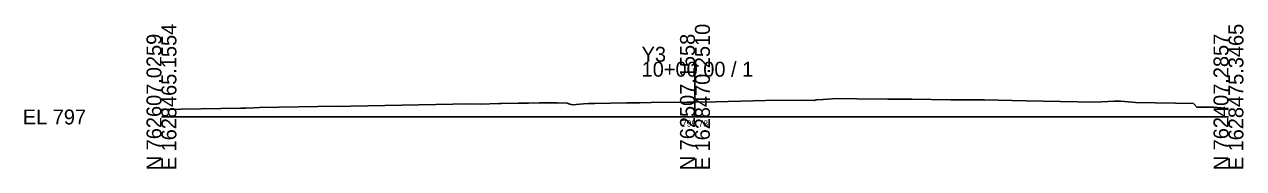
# Model space of a CAD drawing. Extents: x -26 to 203, y -10 to 3017.
# Drawn here: x -25.7 to 202.8, y -9.7 to 17.4 of the extents above; entities that cross this region are included whole.
import ezdxf

# ---------------------------------------------------------------- set-up
doc = ezdxf.new("R2010")
doc.units = 0
for name, color, linetype in [('Default', 7, 'Continuous'), ('Exist Cross Section Cell', 7, 'Continuous'), ('Exist XS Center Line Elevation Label', 7, 'Continuous'), ('Exist XS Ground Line', 7, 'Continuous')]:
    doc.layers.add(name, color=color, linetype=linetype)

msp = doc.modelspace()

# ---------------------------------------------------------------- linework, layer by layer
at = {"layer": 'Exist Cross Section Cell'}
for p, q in [((100, 0), (100, 10.36)), ((0, 0), (100, 0)), ((100, 0), (200, 0))]:
    msp.add_line(p, q, dxfattribs=at)
at = {"layer": 'Exist XS Ground Line'}
msp.add_lwpolyline([(0, 1.42), (14.79, 1.66), (15.52, 1.67), (15.83, 1.67), (17.32, 1.7), (18.38, 1.76), (32.93, 2), (34.46, 1.96), (35.51, 2.05), (57.79, 2.49), (59.8, 2.42), (63.22, 2.5), (63.74, 2.5), (66.86, 2.58), (68.78, 2.62), (70.79, 2.64), (73.11, 2.67), (74.17, 2.67), (76.05, 2.58), (76.55, 2.38), (77.04, 2.27), (79.11, 2.45), (80.03, 2.5), (81.23, 2.53), (87.23, 2.64), (89.68, 2.67), (91.77, 2.69), (98.57, 2.77), (100, 2.78), (103.93, 2.81), (113.21, 3.06), (120.05, 3.16), (122.4, 3.08), (122.75, 3.22), (124.04, 3.25), (126.56, 3.45), (130.39, 3.38), (136.13, 3.37), (140.66, 3.31), (147.97, 3.22), (148.28, 3.19), (154.26, 3.21), (162.1, 3.05), (174.98, 2.78), (178.64, 2.94), (179.85, 2.94), (182.59, 2.73), (190.08, 2.61), (193.46, 2.52), (194.1, 1.86), (194.43, 1.86), (196.22, 1.86), (197.28, 1.86), (198.68, 1.73), (200, 1.59)], dxfattribs=at)

# ---------------------------------------------------------------- texts
at = {"layer": 'Default'}
msp.add_text('-', height=0.0001, dxfattribs=at).set_placement((0, 0))
at = {"layer": 'Exist Cross Section Cell'}
for s, p in [('E 1628465.1554', (2.8, -10)), ('E 1628470.2510', (102.8, -10)), ('E 1628475.3465', (202.8, -10)), ('N 762607.0259', (0, -10)), ('N 762507.1558', (100, -10)), ('N 762407.2857', (200, -10))]:
    msp.add_text(s, height=2.8, rotation=90, dxfattribs=at).set_placement(p)
for s, p in [('Y3', (90, 10.36)), ('10+00.00 / 1', (90, 7.56)), ('EL 797', (-26, -1.4))]:
    msp.add_text(s, height=2.8, dxfattribs=at).set_placement(p)
at = {"layer": 'Exist XS Center Line Elevation Label'}
msp.add_text('799.78', height=1.2, dxfattribs=at).set_placement((97.55, -1.82))

doc.saveas('drawing.dxf')
